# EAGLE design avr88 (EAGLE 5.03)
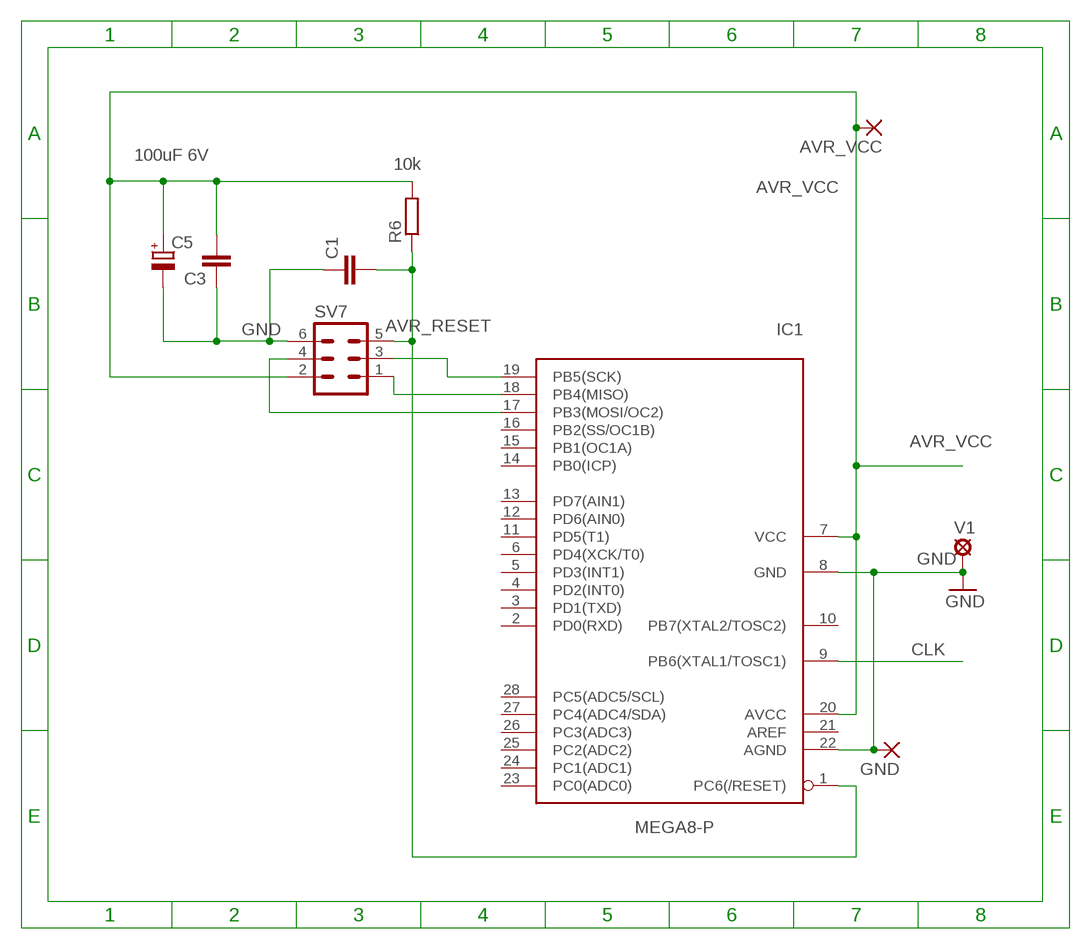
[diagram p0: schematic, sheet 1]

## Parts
AVR_VCC  PAD-TERMINAL  [2,54/1,1]
C1  C5P  [C050-030-075]
C3  C5P  [C050-030-075]
C5  100uF 6V  CPOL1  [E2,5-7---100UF]
GND  PAD-TERMINAL  [2,54/1,1]
IC1  MEGA8-P  [DIL28-3]
R6  10k  R  [0207/10]
SV7  ML6  [ML6]
V1  HOLE-VIA  [LSP10]

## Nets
AVR_RESET: C1.2 IC1.1(PC6(/RESET)) R6.1 SV7.5
AVR_VCC: AVR_VCC.1(P) C3.2 C5.+ IC1.7(VCC) IC1.20(AVCC) R6.2 SV7.2
CLK: IC1.9(PB6(XTAL1/TOSC1))
GND [supply]: C1.1 C3.1 C5.- GND.1(P) IC1.8(GND) IC1.22(AGND) SV7.6 V1.MP
N$2: IC1.19(PB5(SCK)) SV7.3
N$3: IC1.18(PB4(MISO)) SV7.1
N$8: IC1.17(PB3(MOSI/OC2)) SV7.4
Unconnected: IC1.2(PD0(RXD)) IC1.3(PD1(TXD)) IC1.4(PD2(INT0)) IC1.5(PD3(INT1)) IC1.6(PD4(XCK/T0)) IC1.10(PB7(XTAL2/TOSC2)) IC1.11(PD5(T1)) IC1.12(PD6(AIN0)) IC1.13(PD7(AIN1)) IC1.14(PB0(ICP)) IC1.15(PB1(OC1A)) IC1.16(PB2(SS/OC1B)) IC1.21(AREF) IC1.23(PC0(ADC0)) IC1.24(PC1(ADC1)) IC1.25(PC2(ADC2)) IC1.26(PC3(ADC3)) IC1.27(PC4(ADC4/SDA)) IC1.28(PC5(ADC5/SCL))

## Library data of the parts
AVR_VCC GND = ee2parts:PAD-TERMINAL: LARGE THROUGH-HOLE PAD
C1 C3 = ee2parts:C: Capacitor
C5 = ee2parts:CPOL: Electrolytic (polarised) capacitor
IC1 = atmel:MEGA8-P: MICROCONTROLLER 8 Kbytes FLASH, 1 kbytes SRAM, 512 bytes EEPROM, USART, 4-channel 10 bit ADC, 2-channel 8 bit ADC Pin compatible with Atmega48, ATMega88, ATMega168 Source: avr.lbr
R6 = ee2parts:R: Resistor
SV7 = con-harting-ml:ML6: HARTING
V1 = ee2parts:HOLE-VIA: FIXED VIA

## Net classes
1 supply: width 0.635 mm

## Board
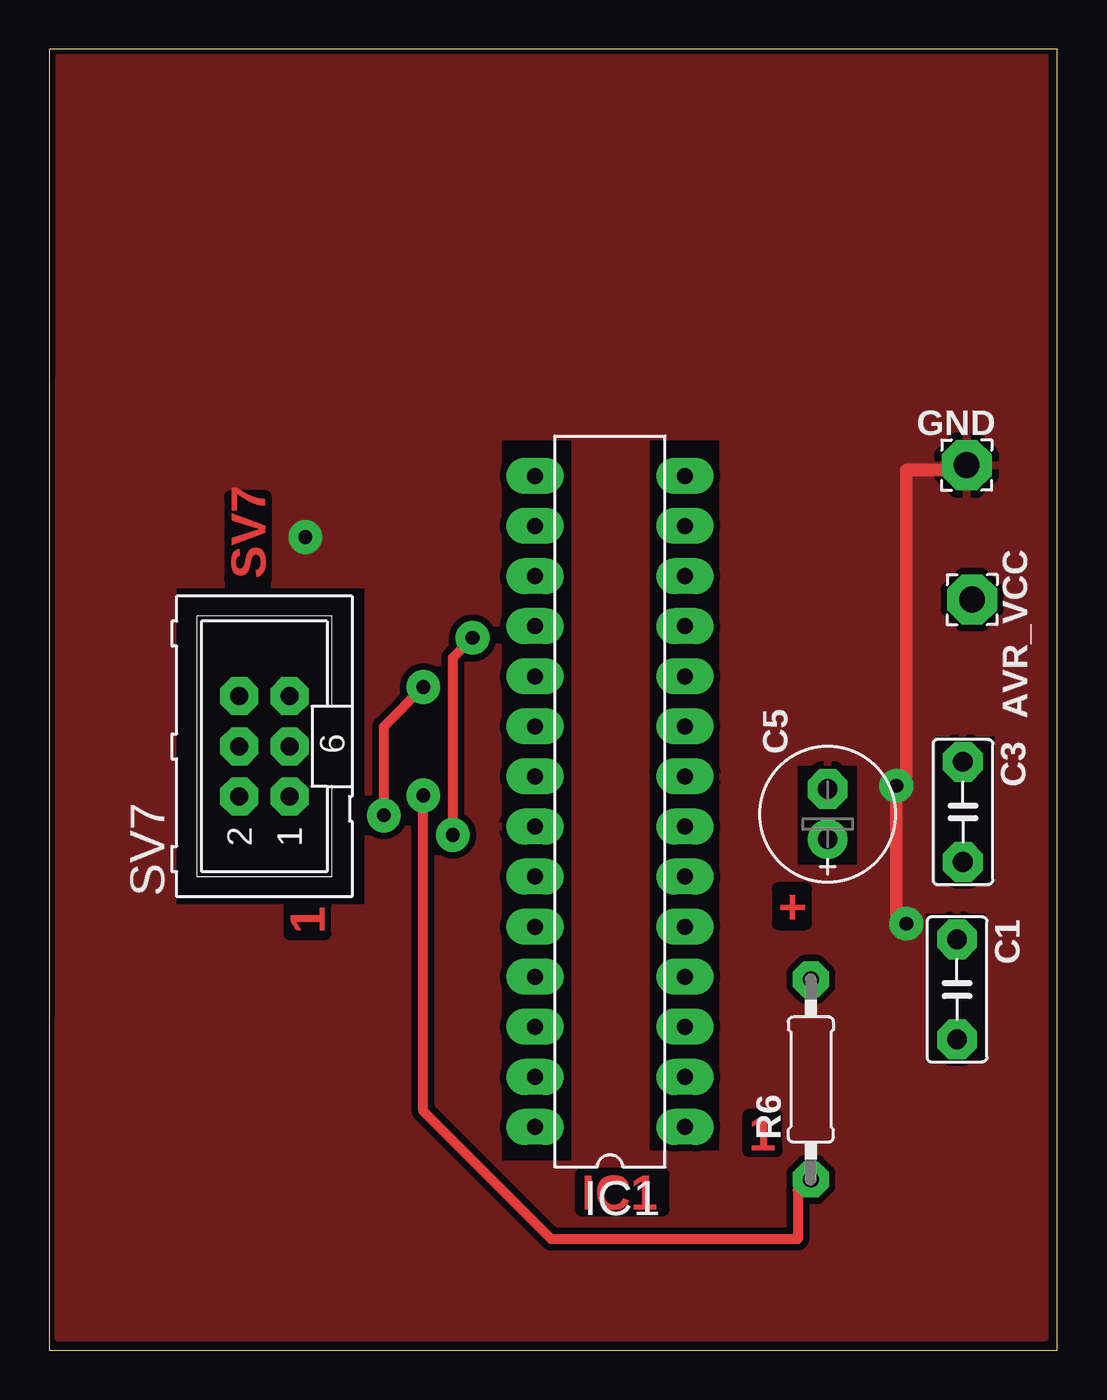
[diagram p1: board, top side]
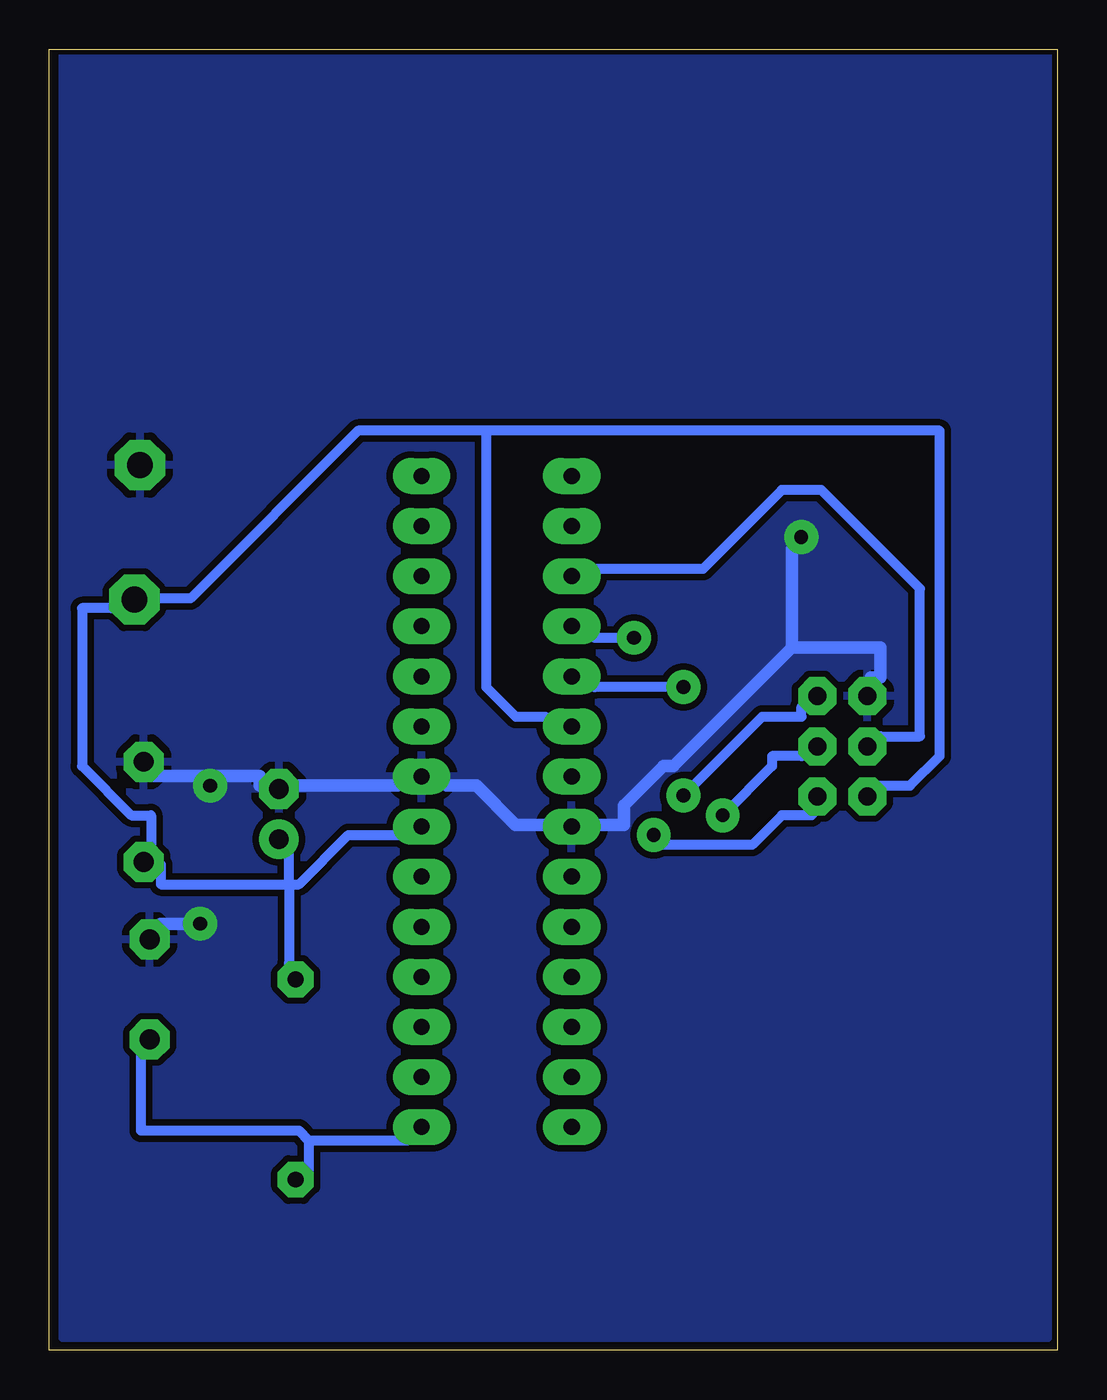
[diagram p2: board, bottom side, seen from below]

Size 51.13 x 65.98 mm. Coordinates in mm from the lower left corner, seen from the top.
Outline: 0,0 51.13,0 51.13,65.98 0,65.98 0,0
Copper layers (1*16): Top 0.035mm / dielectric 1.5mm / Bottom 0.035mm
Design rules "zigbit_rules *": minimum track width 20mil, minimum drill 0.7mm, track to track 13mil, track to pad 13mil, pad to pad 13mil, via to via 13mil, smd to smd 0mil, copper to edge 10mil, drill to drill 10mil, minimum pad ring 20mil, minimum via ring 20mil, stop-mask expansion 0mil, vias tented up to drill 0mil, thermal gap 15mil
tRestrict: area 23,9.6 to 26.5,46.1; area 30.5,10.1 to 34,46.1; area 38,24.6 to 41,29.6; area 44.5,14.6 to 47.5,22.1; area 45,23.6 to 48,31.1; area 6.5,22.6 to 16,38.6

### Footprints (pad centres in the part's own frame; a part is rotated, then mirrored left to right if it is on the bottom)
2,54/1,1 = drill 1.3 pad 2.54 octagon: 1 0,0
C050-030-075 = drill 1 octagon: 1 -2.54,0; 2 2.54,0
E2,5-7---100UF = drill 1 pad 1.6 round: + -1.27,0 | drill 1 pad 1.6 octagon: - 1.27,0
DIL28-3 = drill 0.813 long: 1 -16.51,-3.81; 2 -13.97,-3.81; 3 -11.43,-3.81; 4 -8.89,-3.81; 5 -6.35,-3.81; 6 -3.81,-3.81; 7 -1.27,-3.81; 8 1.27,-3.81; 9 3.81,-3.81; 10 6.35,-3.81; 11 8.89,-3.81; 12 11.43,-3.81; 13 13.97,-3.81; 14 16.51,-3.81; 15 16.51,3.81; 16 13.97,3.81; 17 11.43,3.81; 18 8.89,3.81; 19 6.35,3.81; 20 3.81,3.81; 21 1.27,3.81; 22 -1.27,3.81; 23 -3.81,3.81; 24 -6.35,3.81; 25 -8.89,3.81; 26 -11.43,3.81; 27 -13.97,3.81; 28 -16.51,3.81
0207/10 = drill 0.8 octagon: 1 -5.08,0; 2 5.08,0
ML6 = drill 0.914 octagon: 1 -2.54,-1.27; 2 -2.54,1.27; 3 0,-1.27; 4 0,1.27; 5 2.54,-1.27; 6 2.54,1.27
LSP10 = drill 0.7 pad 1.016 round: MP 0,0

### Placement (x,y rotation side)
AVR_VCC  46.81,38.07 270 top
C1  46.04,18.3 270 top
C3  46.34,27.3 270 top
C5  39.48,27.19 90 top
GND  46.53,44.89 0 top
IC1  28.44,27.83 90 top
R6  38.63,13.73 90 top
SV7  10.91,30.63 90 top
V1  12.99,41.24 0 top

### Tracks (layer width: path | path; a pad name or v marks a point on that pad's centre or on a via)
AVR_RESET  (via drill 0.7)
  Top 0.508: v18.97,28.13 18.97,12.13 25.47,5.63 37.97,5.63 37.97,8.13 R6.1
  Bottom 0.508: 37.97,10.63 37.97,9.13 R6.1 | 37.97,10.63 32.97,10.63 IC1.1 | v18.97,28.13 14.97,32.13 12.97,32.13 12.97,32.63 SV7.5 | 37.97,10.63 38.47,11.13 46.47,11.13 46.47,15.13 C1.2
AVR_VCC
  Bottom 0.508: 38.97,23.63 38.97,25.13 C5.+ | 38.97,23.63 38.97,19.63 R6.2 | 38.97,23.63 38.47,23.63 35.97,26.13 33.47,26.13 IC1.7 | 38.97,23.63 45.47,23.63 45.47,24.63 C3.2 45.97,25.63 45.97,27.13 46.97,27.13 49.47,29.63 49.47,37.63 47.97,37.63 AVR_VCC.1 45.97,38.13 43.97,38.13 35.47,46.63 28.97,46.63 | 28.97,46.63 28.97,33.63 27.47,32.13 25.97,32.13 IC1.20 | 28.97,46.63 5.97,46.63 5.97,30.13 7.47,28.63 8.97,28.63 SV7.2
GND  (via drill 0.7)
  Top 0.635: v43.47,21.63 42.97,22.13 v42.97,28.63 43.47,29.13 43.47,44.63 45.47,44.63 GND.1
  Bottom 0.635: 13.47,35.63 13.47,40.63 V1.MP | 13.47,35.63 8.97,35.63 8.97,34.13 9.47,34.13 SV7.6 | 42.97,29.13 45.97,29.13 C3.1 | 42.97,29.13 40.47,29.13 40.47,28.63 C5.- 38.97,28.63 33.47,28.63 IC1.8 30.97,28.63 29.47,28.63 27.47,26.63 25.97,26.63 IC1.22 23.47,26.63 21.97,26.63 21.97,27.63 19.97,29.63 19.47,29.63 13.47,35.63 | v43.47,21.63 45.47,21.63 C1.1 | 42.97,29.13 v42.97,28.63
  pour Top: 0.53,65.63 50.47,65.63 50.47,0.63 0.47,0.63
  pour Bottom: 0.47,65.63 50.47,65.63 50.47,0.63 0.47,0.63
N$2  (via drill 0.7)
  Top 0.508: v18.97,33.63 16.97,31.63 v16.97,27.13
  Bottom 0.508: v18.97,33.63 23.47,33.63 IC1.19 | v16.97,27.13 14.47,29.63 14.47,30.13 12.97,30.13 SV7.3
N$3  (via drill 0.7)
  Top 0.508: v21.47,36.13 20.47,35.13 v20.47,26.13
  Bottom 0.508: v21.47,36.13 23.47,36.13 IC1.18 | v20.47,26.13 19.97,25.63 15.47,25.63 13.97,27.13 12.47,27.13 SV7.1
N$8
  Bottom 0.508: IC1.17 23.47,39.63 17.97,39.63 13.97,43.63 11.97,43.63 6.97,38.63 6.97,31.13 8.97,31.13 SV7.4

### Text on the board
Top: SV7 | + | 1 | 1 | IC1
